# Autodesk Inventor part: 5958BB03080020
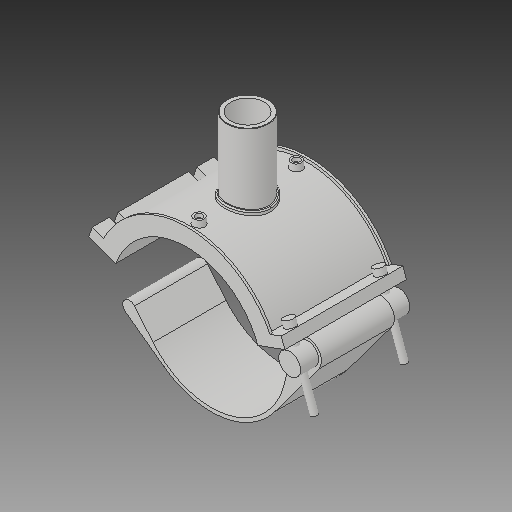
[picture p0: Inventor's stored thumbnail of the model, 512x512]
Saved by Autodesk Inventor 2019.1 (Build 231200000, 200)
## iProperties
Created: 2017-07
Part Number: 5958BB03080020
Material: Generic
Description: PLASSON BRANCH SADDLE 8'' x 2''
Document SubType Name: Modeling
Designer: KIM
Mass: 764.267 g
Surface Area: 1930.38 cm^2
Volume: 764.267 cm^3
Density: 1 g/cm^3
Appearance: Default
Author: KIM
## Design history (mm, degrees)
derived "5958B.ipt"
feature "Solid1::5958B.ipt"
feature "Solid2::5958B.ipt"
feature "Solid3::5958B.ipt"
tag "TaggingFeature1"
body "Solid1"
body "Solid2"
body "Solid3"
other parameters: "d0" = 218.7, "d2" = 233.7816, "d3" = 54.675, "d4" = 176.022, "d5" = 0, "d6" = 0.1, "d8" = 0, "d19" = 6, "d20" = 6, "d21" = 105.6132, "d23" = 0, "d24" = 52.8066, "d26" = 0, "d27" = 3, "d28" = 3, "d29" = 3, "d30" = 72.9, "d31" = 6, "d32" = 0, "d33" = 0, "d34" = 0.6, "d40" = 135.38512, "d41" = 66.11, "d43" = 0, "d45" = 0, "d47" = 235.08, "d48" = 60.1, "d50" = 0, "d70" = 15, "d72" = 0, "d73" = 6, "d75" = 5, "d76" = 0, "d77" = 10.935, "d78" = 139.35, "d79" = 15, "d80" = 70.4088, "d82" = 5 deg, "d84" = 4, "d85" = 14, "d86" = 0, "d87" = 3, "d88" = 0, "d89" = 1, "d90" = 1, "d91" = 140.8176, "d92" = 0, "d93" = 0.5, "d94" = 115.10526, "d96" = 265.56312, "d97" = 3.52044, "d98" = 0, "d102" = 1.803, "d103" = 48.08, "d105" = 0, "d109" = -34.96733, "d117" = 0.601, "d120" = 140 deg, "d121" = 24.228, "d122" = 20 deg, "d123" = 520.712, "d124" = 156.2136, "d126" = 0, "d143" = 229.635, "d150" = 39.366, "d159" = 8.3312, "d161" = 5.4675, "d162" = 105.6132, "d163" = 0, "d167" = 43.74, "d168" = 118.34364, "d173" = 1, "d175" = 109.35, "d176" = 20 deg, "d177" = 15.309, "d178" = 41.656, "d180" = 0, "d185" = 57.20715, "d186" = 57.20715, "d187" = 130.178, "d188" = 12.4968, "d189" = 15.309, "d190" = 0, "d191" = 195.267, "d200" = 20.828, "d202" = 0, "d216" = 158.4198, "d217" = 0, "d221" = 65.12814, "d222" = 15.309, "d223" = 9.1854, "d224" = 109.35, "d225" = 9.1854, "d227" = 31.4928, "d230" = 139.968, "d236" = 11.5 deg, "d238" = 20 deg, "d239" = 15.309, "d240" = 3.52044, "d241" = 0, "d242" = 4.374, "d_" = 218.7, "B_" = 179.832, "H_" = 104.902, "L_" = 176.022, "d_t" = 6, "d_1" = 60.1, "H_1" = 84.074, "d1" = 260.356, "d148" = 5.4675, "d160" = 5.4675
